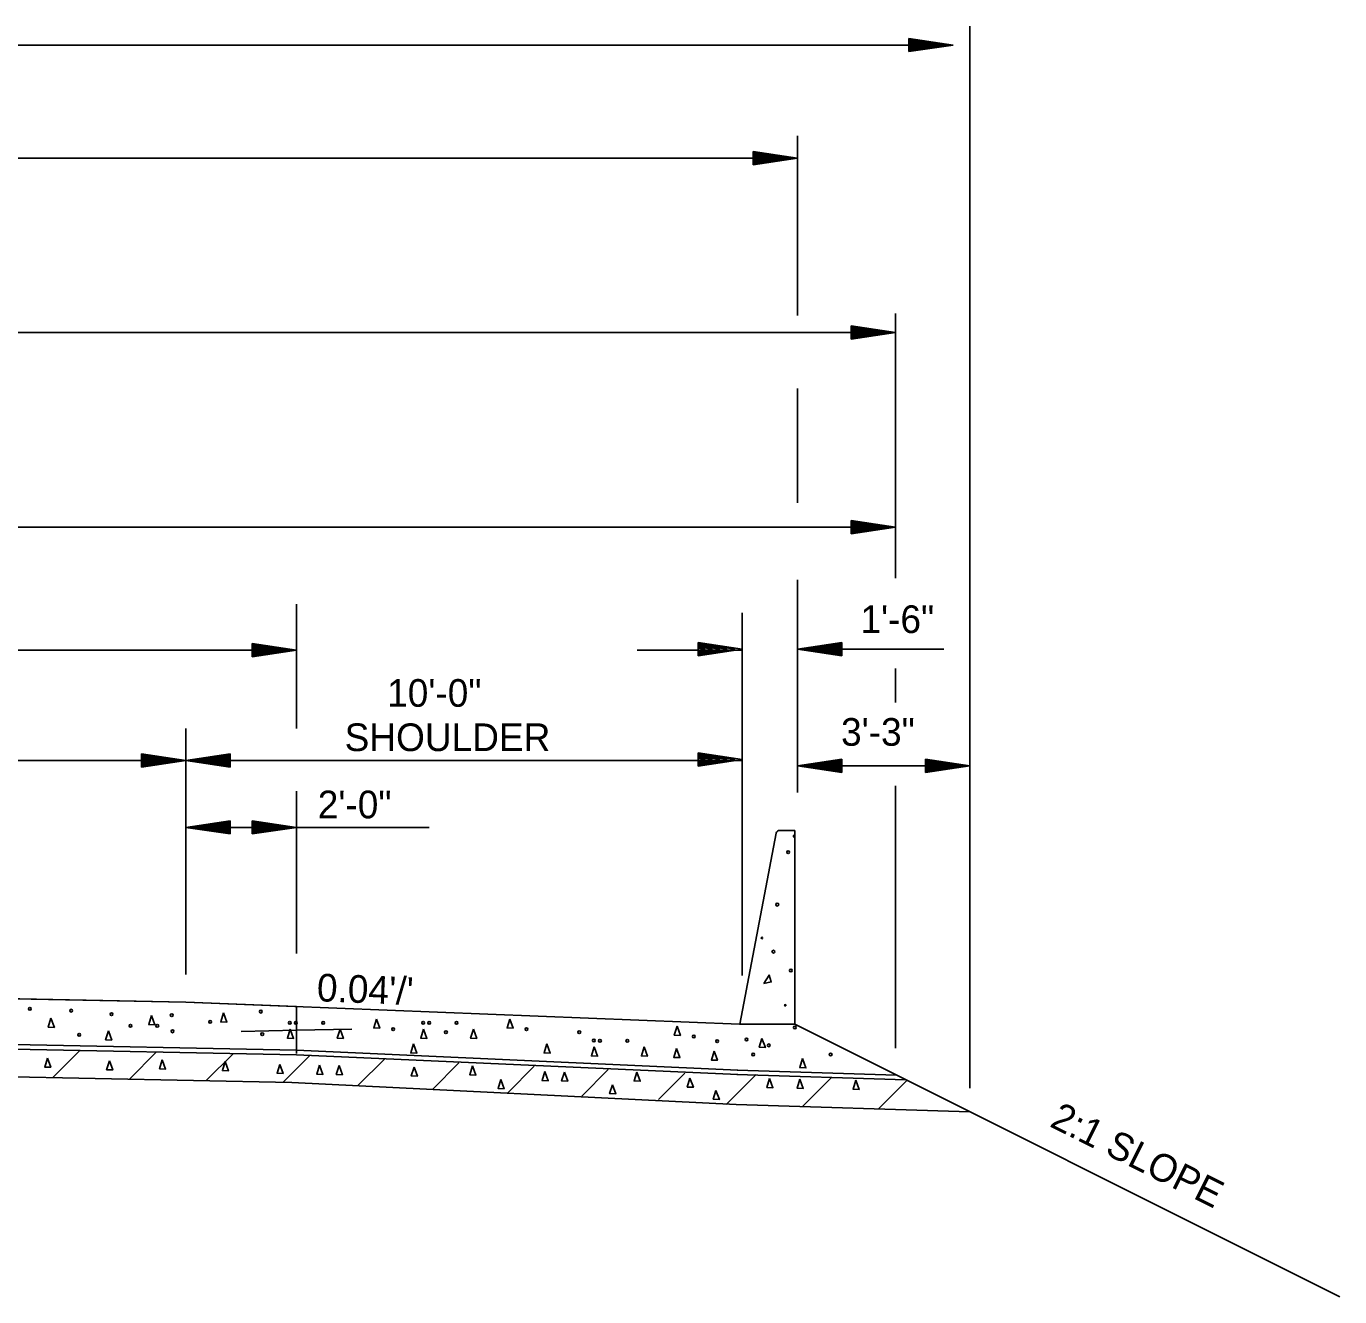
# Model space of a CAD drawing. Extents: x 60325 to 61047, y 53669 to 53767.
# Drawn here: x 60774.69 to 60798.41, y 53687.25 to 53710.19 of the extents above; entities that cross this region are included whole.
import ezdxf

# ---------------------------------------------------------------- set-up
doc = ezdxf.new("R2010")
doc.units = 0
doc.layers.add('R_Border', color=7, linetype='Continuous')
doc.layers.add('R_Border Prem', color=7, linetype='Continuous')

msp = doc.modelspace()

# ---------------------------------------------------------------- linework, layer by layer
at = {"layer": 'R_Border'}
for p, q in [((60779.572, 53697.513), (60779.572, 53699.759)), ((60778.772, 53699.046), (60779.572, 53698.926)), ((60778.772, 53699.046), (60778.772, 53698.806)), ((60778.772, 53699.026), (60779.439, 53698.926)), ((60778.772, 53699.005), (60779.301, 53698.926)), ((60778.772, 53698.985), (60779.168, 53698.926)), ((60778.772, 53698.965), (60779.032, 53698.926)), ((60778.772, 53698.945), (60778.899, 53698.926)), ((60779.572, 53698.926), (60751.572, 53698.926)), ((60778.772, 53698.806), (60779.572, 53698.926)), ((60778.772, 53698.887), (60779.032, 53698.926)), ((60778.772, 53698.846), (60779.301, 53698.926)), ((60778.772, 53698.826), (60779.439, 53698.926)), ((60778.772, 53698.866), (60779.168, 53698.926)), ((60778.772, 53698.907), (60778.899, 53698.926)), ((60777.57, 53693.071), (60777.57, 53697.513)), ((60776.77, 53697.052), (60777.57, 53696.932)), ((60776.77, 53697.052), (60776.77, 53696.812)), ((60777.57, 53696.932), (60753.57, 53696.932)), ((60776.77, 53697.032), (60777.437, 53696.932)), ((60776.77, 53697.011), (60777.299, 53696.932)), ((60776.77, 53696.991), (60777.166, 53696.932)), ((60776.77, 53696.971), (60777.03, 53696.932)), ((60776.77, 53696.951), (60776.897, 53696.932)), ((60776.77, 53696.812), (60777.57, 53696.932)), ((60776.77, 53696.893), (60777.03, 53696.932)), ((60776.77, 53696.852), (60777.299, 53696.932)), ((60776.77, 53696.832), (60777.437, 53696.932)), ((60776.77, 53696.872), (60777.166, 53696.932)), ((60776.77, 53696.913), (60776.897, 53696.932)), ((60779.572, 53693.451), (60779.572, 53696.382)), ((60778.37, 53695.847), (60777.57, 53695.727)), ((60779.57, 53695.727), (60777.57, 53695.727)), ((60778.37, 53695.607), (60777.57, 53695.727)), ((60778.37, 53695.827), (60777.704, 53695.727)), ((60778.37, 53695.627), (60777.704, 53695.727)), ((60778.37, 53695.806), (60777.841, 53695.727)), ((60778.37, 53695.647), (60777.841, 53695.727)), ((60778.37, 53695.786), (60777.975, 53695.727)), ((60778.37, 53695.667), (60777.975, 53695.727)), ((60778.37, 53695.765), (60778.11, 53695.727)), ((60778.37, 53695.687), (60778.11, 53695.727)), ((60778.37, 53695.745), (60778.244, 53695.727)), ((60778.37, 53695.708), (60778.244, 53695.727)), ((60778.37, 53695.847), (60778.37, 53695.607)), ((60778.77, 53695.847), (60779.57, 53695.727)), ((60778.77, 53695.847), (60778.77, 53695.607)), ((60778.77, 53695.827), (60779.437, 53695.727)), ((60778.77, 53695.806), (60779.299, 53695.727)), ((60778.77, 53695.786), (60779.166, 53695.727)), ((60778.77, 53695.765), (60779.03, 53695.727)), ((60778.77, 53695.745), (60778.897, 53695.727)), ((60778.77, 53695.607), (60779.57, 53695.727)), ((60778.77, 53695.687), (60779.03, 53695.727)), ((60778.77, 53695.647), (60779.299, 53695.727)), ((60778.77, 53695.627), (60779.437, 53695.727)), ((60778.77, 53695.667), (60779.166, 53695.727)), ((60778.77, 53695.708), (60778.897, 53695.727)), ((60781.964, 53695.727), (60779.57, 53695.727)), ((60779.572, 53692.48), (60779.572, 53691.646)), ((60780.572, 53692.083), (60779.572, 53692.063)), ((60779.572, 53692.063), (60778.572, 53692.043))]:
    msp.add_line(p, q, dxfattribs=at)
msp.add_lwpolyline([(60751.571, 53692.97), (60753.572, 53693.051), (60777.57, 53692.571), (60779.572, 53692.49)], dxfattribs=at)
at = {"layer": 'R_Border Prem'}
for p, q in [((60791.729, 53694.093), (60791.729, 53710.193)), ((60790.629, 53709.974), (60791.429, 53709.854)), ((60790.629, 53709.974), (60790.629, 53709.734)), ((60790.629, 53709.954), (60791.296, 53709.854)), ((60790.629, 53709.934), (60791.158, 53709.854)), ((60790.629, 53709.914), (60791.025, 53709.854)), ((60790.629, 53709.893), (60790.889, 53709.854)), ((60790.629, 53709.873), (60790.756, 53709.854)), ((60791.429, 53709.854), (60741.764, 53709.854)), ((60790.629, 53709.734), (60791.429, 53709.854)), ((60790.629, 53709.815), (60790.889, 53709.854)), ((60790.629, 53709.775), (60791.158, 53709.854)), ((60790.629, 53709.754), (60791.296, 53709.854)), ((60790.629, 53709.795), (60791.025, 53709.854)), ((60790.629, 53709.835), (60790.756, 53709.854)), ((60788.618, 53704.971), (60788.618, 53708.213)), ((60788.618, 53707.813), (60744.576, 53707.813)), ((60787.818, 53707.933), (60788.618, 53707.813)), ((60787.818, 53707.933), (60787.818, 53707.693)), ((60787.818, 53707.913), (60788.484, 53707.813)), ((60787.818, 53707.893), (60788.346, 53707.813)), ((60787.818, 53707.873), (60788.213, 53707.813)), ((60787.818, 53707.852), (60788.078, 53707.813)), ((60787.818, 53707.832), (60787.944, 53707.813)), ((60787.818, 53707.693), (60788.618, 53707.813)), ((60787.818, 53707.774), (60788.078, 53707.813)), ((60787.818, 53707.734), (60788.346, 53707.813)), ((60787.818, 53707.713), (60788.484, 53707.813)), ((60787.818, 53707.754), (60788.213, 53707.813)), ((60787.818, 53707.794), (60787.944, 53707.813)), ((60790.388, 53700.225), (60790.388, 53705.008)), ((60790.388, 53700.225), (60790.388, 53705.008)), ((60790.388, 53704.661), (60742.805, 53704.661)), ((60789.588, 53704.781), (60790.388, 53704.661)), ((60789.588, 53704.781), (60789.588, 53704.541)), ((60789.588, 53704.761), (60790.254, 53704.661)), ((60789.588, 53704.74), (60790.117, 53704.661)), ((60789.588, 53704.72), (60789.983, 53704.661)), ((60789.588, 53704.699), (60789.848, 53704.661)), ((60789.588, 53704.679), (60789.714, 53704.661)), ((60789.588, 53704.541), (60790.388, 53704.661)), ((60789.588, 53704.621), (60789.848, 53704.661)), ((60789.588, 53704.581), (60790.117, 53704.661)), ((60789.588, 53704.561), (60790.254, 53704.661)), ((60789.588, 53704.601), (60789.983, 53704.661)), ((60789.588, 53704.642), (60789.714, 53704.661)), ((60788.618, 53701.586), (60788.618, 53703.651)), ((60790.388, 53701.145), (60742.805, 53701.145)), ((60789.588, 53701.265), (60790.388, 53701.145)), ((60789.588, 53701.265), (60789.588, 53701.025)), ((60789.588, 53701.245), (60790.254, 53701.145)), ((60789.588, 53701.224), (60790.117, 53701.145)), ((60789.588, 53701.204), (60789.983, 53701.145)), ((60789.588, 53701.183), (60789.848, 53701.145)), ((60789.588, 53701.163), (60789.714, 53701.145)), ((60789.588, 53701.025), (60790.388, 53701.145)), ((60789.588, 53701.105), (60789.848, 53701.145)), ((60789.588, 53701.065), (60790.117, 53701.145)), ((60789.588, 53701.045), (60790.254, 53701.145)), ((60789.588, 53701.085), (60789.983, 53701.145)), ((60789.588, 53701.126), (60789.714, 53701.145)), ((60788.618, 53696.358), (60788.618, 53700.195)), ((60787.621, 53693.05), (60787.621, 53699.599)), ((60786.821, 53699.065), (60787.621, 53698.945)), ((60786.821, 53699.065), (60786.821, 53698.825)), ((60786.821, 53699.045), (60787.488, 53698.945)), ((60786.821, 53699.025), (60787.35, 53698.945)), ((60786.821, 53699.005), (60787.217, 53698.945)), ((60786.821, 53698.984), (60787.081, 53698.945)), ((60786.821, 53698.964), (60786.948, 53698.945)), ((60786.821, 53698.825), (60787.621, 53698.945)), ((60786.821, 53698.906), (60787.081, 53698.945)), ((60786.821, 53698.866), (60787.35, 53698.945)), ((60786.821, 53698.845), (60787.488, 53698.945)), ((60786.821, 53698.886), (60787.217, 53698.945)), ((60786.821, 53698.926), (60786.948, 53698.945)), ((60789.418, 53699.065), (60788.618, 53698.945)), ((60789.418, 53698.825), (60788.618, 53698.945)), ((60788.618, 53698.945), (60791.262, 53698.945)), ((60789.418, 53699.045), (60788.751, 53698.945)), ((60789.418, 53698.845), (60788.751, 53698.945)), ((60789.418, 53699.025), (60788.889, 53698.945)), ((60789.418, 53698.866), (60788.889, 53698.945)), ((60789.418, 53699.005), (60789.022, 53698.945)), ((60789.418, 53698.886), (60789.022, 53698.945)), ((60789.418, 53698.984), (60789.158, 53698.945)), ((60789.418, 53698.906), (60789.158, 53698.945)), ((60789.418, 53698.964), (60789.291, 53698.945)), ((60789.418, 53698.926), (60789.291, 53698.945)), ((60789.418, 53698.825), (60789.418, 53699.065)), ((60787.617, 53698.926), (60785.721, 53698.926)), ((60790.388, 53697.982), (60790.388, 53698.594)), ((60778.37, 53697.052), (60777.57, 53696.932)), ((60778.37, 53696.812), (60778.37, 53697.052)), ((60786.821, 53697.071), (60787.621, 53696.951)), ((60786.821, 53697.071), (60786.821, 53696.831)), ((60786.821, 53697.051), (60787.488, 53696.951)), ((60787.617, 53696.932), (60777.57, 53696.932)), ((60778.37, 53696.812), (60777.57, 53696.932)), ((60778.37, 53697.032), (60777.704, 53696.932)), ((60778.37, 53696.832), (60777.704, 53696.932)), ((60778.37, 53697.011), (60777.841, 53696.932)), ((60778.37, 53696.852), (60777.841, 53696.932)), ((60778.37, 53696.991), (60777.975, 53696.932)), ((60778.37, 53696.872), (60777.975, 53696.932)), ((60778.37, 53696.971), (60778.11, 53696.932)), ((60778.37, 53696.893), (60778.11, 53696.932)), ((60778.37, 53696.951), (60778.244, 53696.932)), ((60778.37, 53696.913), (60778.244, 53696.932)), ((60786.821, 53697.031), (60787.35, 53696.951)), ((60786.821, 53697.011), (60787.217, 53696.951)), ((60786.821, 53696.99), (60787.081, 53696.951)), ((60786.821, 53696.97), (60786.948, 53696.951)), ((60786.821, 53696.831), (60787.621, 53696.951)), ((60786.821, 53696.912), (60787.081, 53696.951)), ((60786.821, 53696.872), (60787.35, 53696.951)), ((60786.821, 53696.851), (60787.488, 53696.951)), ((60786.821, 53696.892), (60787.217, 53696.951)), ((60786.821, 53696.932), (60786.948, 53696.951)), ((60789.418, 53696.959), (60788.618, 53696.839)), ((60789.418, 53696.719), (60788.618, 53696.839)), ((60788.618, 53696.839), (60791.729, 53696.839)), ((60789.418, 53696.939), (60788.751, 53696.839)), ((60789.418, 53696.739), (60788.751, 53696.839)), ((60789.418, 53696.918), (60788.889, 53696.839)), ((60789.418, 53696.759), (60788.889, 53696.839)), ((60789.418, 53696.898), (60789.022, 53696.839)), ((60789.418, 53696.779), (60789.022, 53696.839)), ((60789.418, 53696.878), (60789.158, 53696.839)), ((60789.418, 53696.8), (60789.158, 53696.839)), ((60789.418, 53696.857), (60789.291, 53696.839)), ((60789.418, 53696.82), (60789.291, 53696.839)), ((60789.418, 53696.719), (60789.418, 53696.959)), ((60790.929, 53696.959), (60791.729, 53696.839)), ((60790.929, 53696.959), (60790.929, 53696.719)), ((60790.929, 53696.939), (60791.596, 53696.839)), ((60790.929, 53696.918), (60791.458, 53696.839)), ((60790.929, 53696.898), (60791.325, 53696.839)), ((60790.929, 53696.877), (60791.189, 53696.839)), ((60790.929, 53696.857), (60791.056, 53696.839)), ((60790.929, 53696.719), (60791.729, 53696.839)), ((60790.929, 53696.799), (60791.189, 53696.839)), ((60790.929, 53696.759), (60791.458, 53696.839)), ((60790.929, 53696.739), (60791.596, 53696.839)), ((60790.929, 53696.779), (60791.325, 53696.839)), ((60790.929, 53696.82), (60791.056, 53696.839)), ((60790.388, 53693.768), (60790.388, 53696.479)), ((60788.293, 53695.671), (60788.57, 53695.671)), ((60788.57, 53695.671), (60788.571, 53692.17)), ((60787.574, 53692.17), (60788.232, 53695.621)), ((60791.729, 53691.016), (60791.729, 53694.093)), ((60790.388, 53691.742), (60790.388, 53693.768)), ((60753.57, 53693.051), (60777.57, 53692.571)), ((60777.57, 53692.571), (60787.571, 53692.171)), ((60753.572, 53692.141), (60779.57, 53691.621)), ((60753.574, 53692.22), (60779.57, 53691.701)), ((60787.574, 53692.17), (60788.571, 53692.17)), ((60788.571, 53692.17), (60787.574, 53692.17)), ((60788.571, 53692.17), (60798.41, 53687.251)), ((60753.531, 53691.641), (60779.488, 53691.122)), ((60775.167, 53691.209), (60775.657, 53691.699)), ((60776.554, 53691.181), (60777.044, 53691.671)), ((60777.94, 53691.153), (60778.43, 53691.643)), ((60779.327, 53691.125), (60779.81, 53691.609)), ((60779.57, 53691.701), (60787.541, 53691.342)), ((60779.57, 53691.621), (60787.537, 53691.262)), ((60780.678, 53691.063), (60781.157, 53691.541)), ((60782.025, 53690.995), (60782.503, 53691.474)), ((60783.386, 53690.934), (60783.864, 53691.412)), ((60779.488, 53691.122), (60787.507, 53690.721)), ((60784.721, 53690.874), (60785.199, 53691.352)), ((60786.106, 53690.811), (60786.584, 53691.29)), ((60787.328, 53690.721), (60787.87, 53691.262)), ((60787.523, 53691.262), (60790.574, 53691.169)), ((60787.526, 53691.342), (60790.404, 53691.254)), ((60788.706, 53690.684), (60789.232, 53691.21)), ((60790.078, 53690.642), (60790.595, 53691.159)), ((60787.507, 53690.721), (60791.729, 53690.591))]:
    msp.add_line(p, q, dxfattribs=at)
for points in [[(60788.009, 53692.905), (60788.103, 53693.06), (60788.143, 53692.936), (60788.009, 53692.905)], [(60776.951, 53692.328), (60777.011, 53692.162), (60776.901, 53692.166), (60776.951, 53692.328)], [(60778.252, 53692.376), (60778.313, 53692.21), (60778.203, 53692.215), (60778.252, 53692.376)], [(60775.136, 53692.279), (60775.197, 53692.113), (60775.087, 53692.117), (60775.136, 53692.279)], [(60779.455, 53692.082), (60779.516, 53691.916), (60779.406, 53691.92), (60779.455, 53692.082)], [(60780.357, 53692.082), (60780.417, 53691.916), (60780.307, 53691.92), (60780.357, 53692.082)], [(60781.013, 53692.266), (60781.074, 53692.1), (60780.964, 53692.104), (60781.013, 53692.266)], [(60781.863, 53692.082), (60781.924, 53691.916), (60781.814, 53691.92), (60781.863, 53692.082)], [(60782.765, 53692.082), (60782.825, 53691.916), (60782.715, 53691.92), (60782.765, 53692.082)], [(60783.421, 53692.266), (60783.482, 53692.1), (60783.372, 53692.104), (60783.421, 53692.266)], [(60786.443, 53692.136), (60786.503, 53691.97), (60786.393, 53691.974), (60786.443, 53692.136)], [(60776.173, 53692.052), (60776.233, 53691.886), (60776.123, 53691.891), (60776.173, 53692.052)], [(60787.976, 53691.916), (60788.037, 53691.75), (60787.927, 53691.755), (60787.976, 53691.916)], [(60781.682, 53691.816), (60781.743, 53691.65), (60781.633, 53691.655), (60781.682, 53691.816)], [(60784.09, 53691.816), (60784.151, 53691.65), (60784.041, 53691.655), (60784.09, 53691.816)], [(60784.947, 53691.761), (60785.007, 53691.595), (60784.897, 53691.6), (60784.947, 53691.761)], [(60785.848, 53691.761), (60785.908, 53691.595), (60785.798, 53691.6), (60785.848, 53691.761)], [(60786.433, 53691.734), (60786.494, 53691.568), (60786.384, 53691.573), (60786.433, 53691.734)], [(60787.112, 53691.686), (60787.172, 53691.52), (60787.062, 53691.525), (60787.112, 53691.686)], [(60775.073, 53691.561), (60775.133, 53691.395), (60775.023, 53691.399), (60775.073, 53691.561)], [(60776.191, 53691.512), (60776.251, 53691.346), (60776.141, 53691.351), (60776.191, 53691.512)], [(60777.146, 53691.528), (60777.207, 53691.362), (60777.097, 53691.367), (60777.146, 53691.528)], [(60778.28, 53691.496), (60778.341, 53691.33), (60778.231, 53691.335), (60778.28, 53691.496)], [(60779.269, 53691.447), (60779.329, 53691.281), (60779.219, 53691.286), (60779.269, 53691.447)], [(60779.985, 53691.433), (60780.046, 53691.267), (60779.936, 53691.272), (60779.985, 53691.433)], [(60780.339, 53691.426), (60780.399, 53691.26), (60780.289, 53691.265), (60780.339, 53691.426)], [(60781.692, 53691.399), (60781.752, 53691.233), (60781.642, 53691.238), (60781.692, 53691.399)], [(60782.75, 53691.42), (60782.81, 53691.254), (60782.7, 53691.259), (60782.75, 53691.42)], [(60788.708, 53691.55), (60788.768, 53691.384), (60788.658, 53691.389), (60788.708, 53691.55)], [(60783.26, 53691.174), (60783.32, 53691.008), (60783.21, 53691.012), (60783.26, 53691.174)], [(60784.054, 53691.316), (60784.115, 53691.15), (60784.005, 53691.155), (60784.054, 53691.316)], [(60784.408, 53691.309), (60784.468, 53691.143), (60784.358, 53691.148), (60784.408, 53691.309)], [(60785.717, 53691.309), (60785.777, 53691.143), (60785.667, 53691.148), (60785.717, 53691.309)], [(60786.676, 53691.2), (60786.737, 53691.034), (60786.627, 53691.038), (60786.676, 53691.2)], [(60788.114, 53691.191), (60788.174, 53691.025), (60788.064, 53691.029), (60788.114, 53691.191)], [(60788.659, 53691.18), (60788.72, 53691.014), (60788.61, 53691.018), (60788.659, 53691.18)], [(60789.669, 53691.159), (60789.73, 53690.993), (60789.62, 53690.998), (60789.669, 53691.159)], [(60785.275, 53691.08), (60785.335, 53690.914), (60785.225, 53690.918), (60785.275, 53691.08)], [(60787.145, 53690.978), (60787.206, 53690.812), (60787.096, 53690.816), (60787.145, 53690.978)]]:
    msp.add_lwpolyline(points, dxfattribs=at)
for centre, radius in [((60788.448, 53695.278), 0.0254), ((60788.252, 53694.332), 0.0254), ((60787.975, 53693.729), 0.0127), ((60788.182, 53693.482), 0.0254), ((60788.498, 53693.141), 0.0254), ((60774.756, 53692.449), 0.025), ((60775.501, 53692.417), 0.025), ((60776.23, 53692.352), 0.025), ((60777.316, 53692.336), 0.025), ((60778.924, 53692.399), 0.025), ((60788.396, 53692.515), 0.0127), ((60776.57, 53692.142), 0.025), ((60777.056, 53692.142), 0.025), ((60777.332, 53692.044), 0.025), ((60778.011, 53692.213), 0.025), ((60779.449, 53692.199), 0.025), ((60779.559, 53692.195), 0.025), ((60780.053, 53692.195), 0.025), ((60781.314, 53692.082), 0.025), ((60781.857, 53692.199), 0.025), ((60781.967, 53692.195), 0.025), ((60782.461, 53692.195), 0.025), ((60783.722, 53692.082), 0.025), ((60788.57, 53692.114), 0.025), ((60775.647, 53691.98), 0.025), ((60778.952, 53691.993), 0.025), ((60782.269, 53692.027), 0.025), ((60784.677, 53692.027), 0.025), ((60784.94, 53691.879), 0.025), ((60785.05, 53691.874), 0.025), ((60785.544, 53691.874), 0.025), ((60786.744, 53691.952), 0.025), ((60787.166, 53691.866), 0.025), ((60787.698, 53691.896), 0.025), ((60787.818, 53691.624), 0.025), ((60788.1, 53691.791), 0.025), ((60789.216, 53691.624), 0.025)]:
    msp.add_circle(centre, radius, dxfattribs=at)
msp.add_arc((60788.569, 53695.567), 0.0254, 86.1643, 273.852, dxfattribs=at)
msp.add_ellipse((60788.293, 53695.61), major_axis=(0, 0.0619), ratio=0.9997, start_param=0, end_param=1.382575, dxfattribs=at)

# ---------------------------------------------------------------- texts
at = {"layer": 'R_Border'}
msp.add_text('2\'-0"', height=0.5, dxfattribs=at).set_placement((60779.954, 53695.89))
at = {"layer": 'R_Border Prem'}
for s, p in [('1\'-6"', (60789.754, 53699.236)), ('10\'-0"', (60781.207, 53697.904)), ('SHOULDER', (60780.439, 53697.104)), ('3\'-3"', (60789.404, 53697.2))]:
    msp.add_text(s, height=0.5, dxfattribs=at).set_placement(p)
for s, rotation, p in [("0.04'/'", 357.7094, (60779.931, 53692.588)), ('2:1 SLOPE', 333.4349, (60793.152, 53690.335))]:
    msp.add_text(s, height=0.5, rotation=rotation, dxfattribs=at).set_placement(p)

doc.saveas('drawing.dxf')
